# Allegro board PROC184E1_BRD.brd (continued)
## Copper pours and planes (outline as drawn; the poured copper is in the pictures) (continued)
MCU_ETH_EARTH on TOP: 61.78,9.23 61.78,12.4 85.17,12.4 85.17,9.23 85.15,9.25 81.85,9.25 81.36,9.74 79.15,9.74 78.6,9.18 78.6,0.76 70.9,0.76 70.9,9.25 70.26,9.89 68.28,9.89 67.62,9.23
MCU_ETH_EARTH on BOTTOM: 70.9,0.76 70.9,9.25 70.26,9.89 68.28,9.89 67.62,9.23 61.78,9.23 61.78,12.4 110.83,12.4 110.83,9.23 110.8,9.25 107.5,9.25 107.02,9.74 104.81,9.74 104.25,9.18 104.25,0.76 96.55,0.76 96.55,9.25 95.92,9.89 93.94,9.89 93.28,9.23 87.44,9.23 87.44,9.25 81.85,9.25 81.36,9.74 79.15,9.74 78.6,9.18 78.6,0.76
SW_LM5141 on TOP: 213.29,52.99 221.68,52.99 221.68,62.64 213.29,62.64
SW_LM5141 on BOTTOM: 213.29,52.99 221.04,52.99 221.04,62.64 213.29,62.64
USB0_VBUS_SOC on TOP: 138.62,177.76 138.62,176.28 140.48,176.28 140.48,177.76
USB0_VBUS_SOC on L5-SIGNAL2: 139.29,177.67 140.5,177.67 142.06,176.11 142.06,170.34 146.81,165.59 151.27,165.59 151.27,164.17 145.15,164.17 140.12,169.2 140.12,174.48 139.14,175.45 139.14,177.52
USB_FT2232_EARTH on TOP: 181.19,0.76 181.19,4.83 186.32,4.83 186.32,2.73 189.82,2.73 189.95,2.85 189.95,4.81 193.35,4.81 193.35,0.76
USB_FT4232_EARTH on TOP: 201.7,4.95 206.83,4.95 206.99,4.8 206.99,3.35 207.22,3.12 210.24,3.12 210.54,3.43 210.54,4.62 210.7,4.78 213.84,4.78 213.9,4.72 213.9,1.07 213.62,0.79 203.56,0.79 203.53,0.76 201.75,0.76 201.37,1.14 201.37,4.62
USB_TYPEA_EARTH1 on BOTTOM: 33.77,186.66 33.77,180.83 39.45,180.83 39.45,186.66
USB_TYPEA_EARTH1 on L7-SIGNAL3: 36.23,188.78 36.23,176.89 39.71,176.89 39.71,182.07 41.21,183.57 47.74,183.57 49.13,182.18 49.13,176.89 52.74,176.89 52.74,188.78
USBC_EARTH on TOP: 143.54,186.37 143.54,189.74 156.73,189.74 156.73,186.37
USBC_EARTH on BOTTOM: 143.72,181.62 143.72,189.74 157.16,189.74 157.16,186.75 155.3,186.75 155.3,181.64 155.28,181.62 152.76,181.62 152.76,186.39 145.8,186.39 145.8,181.62
USBC_PD_SW on TOP (solid shape): 172.92,176 173.03,175.95 173.12,175.94 173.86,175.94 173.92,175.94 173.99,175.96 174.11,175.96 174.15,175.95 174.16,175.91 174.16,174.12 174.15,174.09 174.11,174.07 173.41,174.07 173.38,174.04 173.38,174.04 173.33,174.04 173.31,174.03 173.3,174.02 173.22,173.95 173.21,173.94 173.19,173.93 172.17,173.93 172.13,173.95 172.12,173.98 172.12,175.94 172.13,175.98 172.17,176
USBC_PD_SW on BOTTOM (solid shape): outline of 631 points within 161.7,173.82 173.82,179.99
V_3V3 on TOP: 170.06,169.27 184.46,169.27 184.46,162.97 174.86,162.97 172.78,160.89 172.78,140.55 175.45,137.88 184.51,137.88 184.51,131.45 165.03,131.45 165.03,164.24
V_3V3 on BOTTOM, L7-SIGNAL3: 170.06,169.27 184.46,169.27 184.46,162.97 174.86,162.97 172.78,160.89 172.78,140.55 175.45,137.88 184.51,137.88 184.51,131.63 168.66,131.63 165.03,135.26 165.03,164.24
V_12V0 on TOP: 227.14,64.79 232.85,64.79 232.85,72.04 227.14,72.04
VBUS_5V_WIFI/BT on TOP: 131.33,188.74 131.33,184.56 133.43,184.56 133.43,188.74
VBUS_5V_WIFI/BT on BOTTOM: 130.74,188.65 130.74,181.47 134.07,181.47 134.07,188.65
VBUS_5V_WIFI/BT on BOTTOM: 137.99,178.09 137.99,176.99 137.4,176.99 137.4,176.11 139.09,176.11 139.09,178.09
VBUS_5V_WIFI/BT on L8-PWR1: 130.81,188.62 134.24,188.62 134.24,184.68 137.98,180.94 137.98,178.47 139,177.45 139,174.28 133.92,174.28 130.81,177.38
VCAP_VDDS2 on L14-SIGNAL6: 101.58,75.51 104.76,75.51 106.36,77.11 111.29,77.11 112.4,78.23 112.4,78.99 112.2,79.2 105.42,79.2 104.91,78.69 102.73,78.69 101.58,77.55
VCOMAD on L12-SIGNAL5: 21.83,27.54 41.49,27.54 41.49,24.62 39.4,22.54 29.62,22.54 29.62,19.64 31.76,19.64 32.19,19.21 32.19,11.89 30.69,11.89 30.69,14.94 26.88,18.75 26.88,24.54 22.84,24.54 22.31,24.01 22.31,15.12 19.19,15.12 19.19,24.9
VDA_DLL_MMC0_0V8 on BOTTOM: 157.06,103.31 157.06,102.67 159.7,102.67 159.7,103.31
VDA_DSITX_0V8 on BOTTOM: 116.75,107.8 117.97,107.8 118.09,107.67 118.09,106.3 117.97,106.17 116.8,106.17 116.42,106.55 115.38,106.55 115.38,107.44 116.39,107.44
VDA_MCU_1V8 on L8-PWR1: 112.13,75.98 101.05,75.98 99.39,74.32 99.07,74.32 99.07,47.7 107.25,39.52 115.71,39.52 116.44,38.79 131.15,38.79 132.29,37.64 163.96,37.64 164.29,38.02 175.72,49.45 175.72,50.21 182.61,57.11 182.61,74.02 178.88,77.76 169.64,77.76 169.35,77.47 169.35,53.5 158.91,43.06 144.31,43.06 140.34,47.02 140.34,57.13 128.35,69.11 116.57,69.11 114.77,70.92 114.77,75.72 114.51,75.98 114.49,75.98 114.06,76.4 112.56,76.4
VDA_PHY_1V8 on TOP: 106.43,111.78 106.43,109.72 108.28,109.72 108.28,111.78
VDA_PHY_1V8 on BOTTOM: 106.02,112.36 106.02,109.04 108.07,109.04 108.07,110.81 107.79,111.09 106.97,111.09 106.97,112.36
VDA_PHY_1V8 on L9-PWR2: 136.53,114.03 136.53,110.91 116.93,110.91 115.34,109.32 108.31,109.32 108.01,109.02 107.17,109.02 106.55,109.65 106.55,111.86 106.96,112.26 108.2,112.26 108.74,112.8 112.14,112.8 113.37,114.03
VDA_PHY_1V8 on L14-SIGNAL6: 155.62,107.16 155.62,102.7 170.82,102.7 170.82,107.16
VDA_PHY_1V8_REG on TOP: 108.8,115.16 107.83,115.16 107.83,114.45 106.41,114.45 106.41,112.05 108.8,112.05
VDA_PLL_1V8 on TOP: 87.98,82.14 90.86,82.14 90.86,84.05 87.98,84.05
VDA_PLL_1V8 on L12-SIGNAL5: 127.59,88.4 118.19,88.4 118.18,88.38 96.37,88.38 96.12,88.14 89.37,88.14 87.31,86.08 87.31,84.58 88.5,83.39 109.91,83.39 112.45,80.85 112.45,79.27 111.62,78.44 111.62,76.33 111.84,76.1 112.4,76.1 113.9,77.6 118.47,77.6 120.86,75.21 126.7,75.21 127.59,76.1
VDA_PLL_1V8_REG on TOP: 87.69,83.41 85.77,83.41 85.77,80.96 86.84,80.96 86.84,81.99 87.02,82.16 87.69,82.16
VDA_PLL_DDR1_0V8 on L10-SIGNAL4: 124.39,74.7 124.39,66.8 133.94,57.25 137.9,57.25 138.36,57.71 138.36,61.09 128.76,70.69 127.82,70.69 126.73,71.78 126.73,74.8 126.2,75.34 125.03,75.34
VDA_SERDES0_1_0V8 on BOTTOM: 134.46,107.75 135.89,107.75 135.89,106.19 134.52,106.19 134.17,106.54 133.11,106.54 133.11,107.45 133.14,107.48 134.19,107.48
VDA_SERDES0_1_0V8 on L9-PWR2: 134.2,107.08 136.43,107.08 136.43,93.96 131.02,88.54 124.42,88.54 123.91,89.05 123.91,89.69 124.29,90.07 124.67,90.07 125.18,89.56 126.2,89.56 133.31,96.67 133.31,106.19
VDA_SERDES0_1_1V8 on L9-PWR2: 130,101.3 130,107.07 131.94,107.07 132.93,106.08 132.93,96.93 127.47,91.47 127.47,91.08 126.2,89.81 124.93,89.81 124.93,91.73 126.07,92.86 126.07,97.37
VDA_SERDES4_0V8 on L9-PWR2: 126.24,104.83 126.44,105.03 126.44,105.66 127.81,107.04 129.28,107.04 129.5,106.83 129.5,103.84 128.48,102.83 126.14,102.83 123.84,100.52 123.78,98.87 123.78,93.31 124.29,92.8 124.29,90.7 123.15,89.56 121.39,89.56 120.56,90.4 120.56,102.29 123.1,104.83
VDA_SERDES_C0_1_0V8 on BOTTOM: 145.37,103.51 145.75,103.53 145.75,103.02 148.29,103.02 148.29,103.4 149.36,103.41 149.36,101.63 145.37,101.63
VDA_SERDES_C0_1_0V8 on L14-SIGNAL6: 123.88,89.15 123.88,88.62 125.23,87.27 129.7,87.27 130.46,86.51 138.24,86.51 141.05,89.33 141.05,96.55 144.84,100.33 146.08,100.33 147.23,101.47 147.23,101.85 146.9,102.18 144.05,102.18 139.61,97.74 139.61,89.94 137.55,87.88 131.33,87.88 129.57,89.64 124.37,89.64
VDA_UFS_0V8 on BOTTOM: 150.15,103.31 150.15,102.67 152.79,102.67 152.79,103.31
VDA_UFS_1V8 on BOTTOM: 153.6,103.31 153.6,102.67 156.24,102.67 156.24,103.31
VDA_USB_3V3_REG on BOTTOM: 117.43,116.09 117.43,117.05 118.14,117.05 118.14,118.47 119.95,118.47 119.95,116.09
VDA_USB_3V3_SEL on BOTTOM: 120.26,118.16 122.06,118.16 122.06,116.3 120.26,116.3
VEXP_3V3 on TOP: 203.06,125.53 203.06,118.52 217.86,118.52 217.86,126.7 205.88,126.7 205.88,125.53
VMAIN on TOP, L5-SIGNAL2, L10-SIGNAL4, L12-SIGNAL5, L14-SIGNAL6: 210.75,160.66 210.75,144.56 231.96,144.56 231.96,160.66
VMAIN on BOTTOM: 210.75,160.69 210.75,146.96 212.08,146.96 214.49,144.56 231.96,144.56 231.96,160.69
VMAIN on L3-SIGNAL1: 210.75,160.66 210.75,144.51 208.47,142.22 208.47,140.16 207.45,139.15 206.21,139.15 206.21,136.35 206.38,136.18 215.65,136.18 215.65,143.19 217.05,144.58 231.89,144.58 231.89,160.66
VMAIN on L7-SIGNAL3: 210.75,160.71 210.75,149.77 215.86,144.66 231.89,144.66 231.89,160.71
VMAIN_CONN on L3-SIGNAL1, L7-SIGNAL3, L8-PWR1, L10-SIGNAL4, L12-SIGNAL5, L14-SIGNAL6: 228.79,169.58 228.79,180.7 217.86,180.7 217.86,175.67 212.66,175.67 212.66,185.88 206.41,185.88 206.41,169.6 206.43,169.58
VMAIN_CONN on L5-SIGNAL2: 206.41,177.34 206.41,185.88 212.66,185.88 212.66,175.67 217.86,175.67 217.86,180.7 228.79,180.7 228.79,170.31 228.51,170.03 213.72,170.03
VMAIN_CONN on L9-PWR2: 228.79,169.55 228.79,180.7 217.66,180.7 217.66,175.67 212.63,175.67 212.63,185.88 206.41,185.88 206.41,175.88 212.73,169.55
VMAIN_FUSE on TOP: 215.22,161.3 228.79,161.3 228.79,168.94 208.49,168.94 208.49,165.31 209.07,165.31 209.07,166.63 210.19,166.63 210.19,165.18 215.22,165.18
VMAIN_FUSE on BOTTOM, L3-SIGNAL1, L8-PWR1, L10-SIGNAL4, L12-SIGNAL5, L14-SIGNAL6: 228.79,161.32 228.79,168.94 208.87,168.94 208.87,161.32
VMAIN_FUSE on L5-SIGNAL2: 228.79,161.32 228.79,168.83 208.87,168.83 208.87,161.32
VMAIN_FUSE on L7-SIGNAL3: 228.79,161.32 228.79,168.94 209.04,168.94 209.04,161.32
VMAIN_FUSE on L9-PWR2: 219.13,161.32 228.82,161.32 228.82,168.94 212.4,168.94 212.4,168.05
VPP_EFUSE_1V8 on TOP: 88.32,74.82 88.32,73.06 90.14,73.06 90.14,73.72 90.31,73.89 91.12,73.89 91.12,74.82
VPP_MCU_1V8 on L10-SIGNAL4: 105.39,70.47 109.14,70.47 111.03,72.37 113.39,72.37 113.95,71.81 113.95,68.43 112.3,66.78 100.87,66.78 100.67,66.98 100.67,66.99 100.44,67.22 100.43,67.22 99.67,67.98 99.67,68.5 103.42,68.5
VSYS_3V3 on TOP: 117.38,29.07 122.41,29.07 122.41,30.54 121.12,30.54 120.71,30.13 117.38,30.13
VSYS_3V3 on TOP: 112.28,118.52 111.06,119.74 78.14,119.74 78.14,130.97 141.59,130.97 143.82,133.21 143.82,141.03 149.44,146.64 149.44,156.6 164.65,156.6 164.65,131.42 161.59,131.42 160.08,129.9 160.08,118.52
VSYS_3V3 on TOP: 139.91,24.06 142.93,24.06 142.93,21.69 141.21,21.69 140.83,21.3 140.83,21.06 140.72,20.96 139.91,20.96
VSYS_3V3 on TOP: 29.83,129.18 29.83,123.76 31.3,123.76 31.3,125.38 32.36,126.44 65.56,126.44 65.56,129.18
VSYS_3V3 on TOP: 117.38,21.62 121.37,21.62 122.41,22.66 122.41,30.54 121.06,30.54 121.06,23.12 120.63,22.69 117.38,22.69
VSYS_3V3 on TOP: 12.97,134.22 12.97,133.14 15.47,133.14 15.47,134.22
VSYS_3V3 on BOTTOM: 154.14,156.45 154.14,149.16 153.98,149 153.98,139.96 164.42,139.96 164.42,156.45
VSYS_3V3 on BOTTOM: 86.22,127.74 82.19,127.74 82.19,128.81 86.22,128.81
VSYS_3V3 on BOTTOM: 12.94,135.21 12.94,133.08 15.55,133.08 15.55,135.21
VSYS_3V3 on L7-SIGNAL3: 61.72,127.73 64.85,127.73 65.72,126.85 65.72,112.43 67.27,110.88 67.27,105.55 61.72,105.55
VSYS_3V3 on L10-SIGNAL4: 143.14,156.7 194.93,156.7 219.19,132.44 219.19,129.06 222.28,125.97 222.28,92.74 186.52,92.74 184.46,94.8 184.46,102.7 198.18,102.7 198.18,117.38 192.77,122.79 156.65,122.79 143.14,136.3
VSYS_3V3 on L10-SIGNAL4: outline of 95 points within 45.58,3.94 240.24,189.59 ; 7 cut-outs
VSYS_3V3 on L12-SIGNAL5: 13.3,134.32 15.61,134.32 20.51,129.42 32.9,129.42 33.18,129.14 33.18,126.32 32.96,126.1 19.12,126.1 13.06,132.16 13.06,134.09
VSYS_5V0 on TOP: 221.29,90.51 221.29,82.2 226.37,82.2 226.37,85.07 227.47,85.07 227.47,90.51
VSYS_5V0 on TOP: 55.38,21.52 55.38,19.62 56.88,19.62 56.88,21.52
VSYS_5V0 on TOP: 73.29,91.02 72.14,91.02 71.89,90.76 69.1,90.76 69.1,92.29 72.14,92.29 72.14,91.52 73.29,91.52
VSYS_5V0 on TOP: 41,30.64 41,29.55 45.37,29.55 45.37,30.64
VSYS_5V0 on TOP: 24.29,7.58 24.29,3.72 25.74,3.72 25.74,7.58
VSYS_5V0 on TOP: 58.73,10.19 58.73,9.3 61.65,9.3 61.65,10.19
VSYS_5V0 on BOTTOM: 113.66,118.3 115.48,118.3 115.48,117.11 115.88,116.71 115.88,116.15 114.7,116.15 114.7,116.5 114.45,116.76 113.66,116.76
VSYS_5V0 on BOTTOM: 179.64,21.55 179.64,22.84 174.96,22.84 174.96,21.55
VSYS_5V0 on BOTTOM: 132.62,168.99 135.82,168.99 135.82,167.93 132.62,167.93
VSYS_5V0 on BOTTOM: 55.53,180.68 57.95,180.68 58.86,179.76 59.95,179.76 59.95,178.14 57.11,178.14 57.01,178.24 57.01,179.13 56.47,179.66 55.53,179.66
VSYS_5V0 on BOTTOM: 140.72,178.09 145.47,178.09 145.47,176.59 143.32,176.59 143.32,177.27 140.72,177.27
VSYS_5V0 on BOTTOM: 108.31,169.86 108.31,166.66 107.25,166.66 107.25,169.86
VSYS_5V0 on BOTTOM: 38.79,61.26 41.33,61.26 41.61,61.54 43.24,61.54 43.24,59.21 41.54,59.21 41.54,59.77 41.32,59.99 38.79,59.99
VSYS_5V0 on L7-SIGNAL3: 70.87,91.83 70.87,91.12 70.42,90.66 68.79,90.66 67.95,91.5 67.95,97.82 69.05,98.92 69.05,131.22 74.99,137.17 83.8,137.17 84.21,136.76 84.21,135.34 83.3,134.42 77.53,134.42 71.05,127.95 71.05,92.01
VSYS_5V0 on L9-PWR2: 24.29,3.39 24.29,15.02 28.99,19.72 28.99,63.15 41.39,75.55 41.39,117.48 53.48,117.48 53.48,66.94 43.62,57.08 43.62,36.63 84.77,36.63 93.86,27.54 107.91,27.54 108.97,26.47 128.35,26.47 129.4,25.43 140.37,25.43 140.88,25.94 157.34,25.94 157.84,25.43 169.81,25.43 170.48,24.76 186.36,24.76 188.68,27.08 218.12,27.08 229.55,38.51 229.55,79.92 227.59,81.87 219.08,81.87 219.08,128.46 181.26,166.28 98.69,166.28 96.66,168.31 44.92,168.31 44.92,188.29 192.55,188.29 211.34,169.5 211.34,167.72 218.88,160.18 223.91,160.18 242.86,141.23 242.86,9.4 236.85,3.39
VSYS_5V0 on L10-SIGNAL4: 69.22,94.21 72.95,97.94 75.95,97.94 101.57,123.57 107.17,123.57 107.17,122.91 91.42,107.17 91.42,103.44 88.38,100.39 85.92,100.39 79.21,93.68 73.7,93.68 73.16,93.15 73.16,91.68 72.3,90.81 69.22,90.81
VSYS_GPIORET_5V0 on TOP: 165.92,22.51 167.62,22.51 167.7,22.59 169.96,22.59 169.96,21.98 168.99,21.98 168.61,21.6 165.92,21.6
VSYS_GPIORET_IO_3V3 on BOTTOM: 80.76,67.55 80.76,66.48 80.63,66.35 80.63,64.73 81.9,64.73 81.9,67.42 81.77,67.55
VSYS_IO_1V8 on TOP: 54.26,108.64 55.69,108.64 55.69,109.61 54.26,109.61
VSYS_IO_1V8 on TOP: 101.38,156.01 101.38,151.44 102.24,151.44 102.24,156.01
VSYS_IO_1V8 on TOP: 61.43,109.92 60.61,109.92 60.61,108.26 61.43,108.26
VSYS_IO_1V8 on TOP: 167.95,89.82 170.62,89.82 170.62,88.55 169.86,87.79 169.86,87.28 169.73,87.15 167.95,87.15
VSYS_IO_1V8 on BOTTOM: 38.79,70.26 41.33,70.26 41.61,70.54 43.32,70.54 43.32,68.08 41.54,68.08 41.54,68.74 41.28,68.99 38.79,68.99
VSYS_IO_1V8 on BOTTOM: 139.58,157.87 139.58,154.46 139.86,154.19 140.27,154.19 140.5,154.41 140.5,154.97 140.62,155.1 140.95,155.1 141.49,155.63 142.5,155.63 142.5,157.87
VSYS_IO_1V8 on BOTTOM: 179.69,100.34 179.69,97.75 180.78,97.75 180.78,100.34
VSYS_IO_1V8 on L7-SIGNAL3: 104.31,163.91 104.31,152.28 103.54,151.51 83.05,151.51 83.05,151.54 77.45,151.54 77.45,151.37 69.55,143.46 69.55,137.59 66.72,134.76 66.72,130.53 64.55,128.37 61.11,128.37 61.11,107.27 54.2,107.27 54.2,131.12 57.03,133.94 57.03,140.55 80.38,163.91
VSYS_IO_1V8 on L8-PWR1: 152.08,175.67 204.91,175.67 204.91,167.93 178.11,167.93 175.89,165.7 175.89,158.29 173.85,156.24 82.33,156.24 80.63,157.94 80.63,169.25 82.79,171.41 147.81,171.41
VSYS_IO_1V8 on L10-SIGNAL4: 55.06,111.06 61.63,111.06 61.63,108.09 60,106.46 60,106.46 57.13,106.46 54.19,103.51 54.19,85.58 48.24,79.64 48.24,73.84 44.83,70.44 44.83,67.78 41.89,67.78 41.89,72.71 43.67,74.48 43.67,86.44 49.18,91.96 49.18,105.19
VSYS_IO_1V8 on L10-SIGNAL4: 183.78,97.16 174.46,97.16 172.73,95.44 172.73,88.04 168.33,88.04 167.57,88.81 167.57,102.67 183.78,102.67
VSYS_IO_1V8 on L14-SIGNAL6: 178.57,109.28 173.29,114.56 163.69,114.56 160.94,117.3 160.94,129.7 163.53,132.29 163.53,154.16 160.66,157.03 154.49,157.03 151.16,160.36 138.39,160.36 137.75,159.72 137.75,154.69 152.31,140.14 152.31,138.64 154.75,136.2 154.85,136.2 154.85,112.12 159.11,107.86 170.95,107.86 171.51,107.3 171.51,102.75 167.52,98.76 167.52,88.32 167.9,87.94 173.01,87.94 178.57,93.5
VSYS_IO_3V3 on TOP: 78.27,169.4 78.27,167.22 80.4,167.22 80.42,167.24 80.42,168.49 79.13,168.49 79.13,169.4
VSYS_IO_3V3 on TOP: 59.95,178.67 59.95,175.27 61.58,175.27 61.58,178.67
VSYS_IO_3V3 on TOP: 53.2,124.19 53.2,122.69 54.62,122.69 54.62,124.19
VSYS_IO_3V3 on TOP: 73.97,81.29 76.5,81.29 76.5,85.29 74.69,87.1 57.87,87.1 57.87,82.91 72.35,82.91
VSYS_IO_3V3 on TOP: 65.64,122.92 65.64,121.42 66.53,121.42 66.53,122.92
VSYS_IO_3V3 on BOTTOM: 132.65,157.2 131.3,157.2 131.3,162.29 132.65,162.29
VSYS_IO_3V3 on BOTTOM: 38.79,66.76 38.79,65.51 41.41,65.51 41.56,65.36 42.27,65.36 42.27,66.89 41.49,66.89 41.36,66.76
VSYS_IO_3V3 on BOTTOM: 152.43,151.8 153.78,151.8 153.78,157.31 154.24,157.77 156.4,157.77 156.4,160.18 152.43,160.18
VSYS_IO_3V3 on BOTTOM: 175.93,102.6 180.02,102.6 180.02,101.68 177.61,101.68 177.35,101.43 175.93,101.43
VSYS_IO_3V3 on BOTTOM: 136.79,28.13 136.79,24.39 137.96,24.39 137.96,28.13
VSYS_IO_3V3 on L7-SIGNAL3: 212.96,42.2 212.96,51.75 209.23,55.48 209.23,98.58 201.35,98.58 201.35,65.82 195.89,60.36 193.35,60.36 192.34,61.37 192.34,63.28 197.93,68.87 197.93,88.42 187.26,99.09 177.66,99.09 177.66,102.9 207.81,102.9 208.67,103.77 208.67,108.47 219.39,108.47 219.39,91.09 221.42,89.06 221.42,42.2
VSYS_IO_3V3 on L9-PWR2: 54.11,86.86 61.68,86.86 67.5,81.04 67.5,60.54 60.54,53.58 60.54,41.28 44.51,41.28 44.51,56.93 54.11,66.53
VSYS_IO_3V3 on L10-SIGNAL4: outline of 81 points within 6.37,1.35 220.28,189.06
VSYS_MCU_5V0 on TOP: 134.88,20.56 136.3,20.56 136.48,20.73 138.39,20.73 138.39,20.12 137.42,20.12 137.04,19.74 136.08,19.74 136.08,18.96 134.88,18.96
VSYS_MCU_5V0 on BOTTOM: 132.09,20.51 137.91,20.51 140.39,18.02 140.39,16.39 140.17,16.16 139.58,16.16 139.38,16.37 139.38,17.23 137.75,18.85 132.39,18.85 130.62,17.08 130.62,16.31 130.36,16.06 129.75,16.06 129.52,16.29 129.52,17.94
VSYS_MCU_5V0 on L7-SIGNAL3: 117.38,27.05 117.38,23.4 117.57,23.21 118.93,23.21 118.93,24.29 121.47,24.29 121.47,18.32 122.23,17.56 126.58,17.56 126.58,16.17 131.96,16.17 131.96,18.71 138.13,18.71 138.52,18.32 138.52,16.24 141.55,16.24 141.55,23.69 128.22,23.69 127.04,22.51 125.79,22.51 125.79,26.76 124.9,27.65 117.98,27.65
VSYS_MCUIO_1V8 on TOP: 165.25,69.45 165.25,68.21 166.58,68.21 166.58,69.45
VSYS_MCUIO_1V8 on L3-SIGNAL1: 130.08,41.02 130.08,38.1 130.64,37.54 135.75,37.54 137.97,39.76 142.79,39.76 145.17,42.14 145.17,47.37 144.86,47.68 144,47.68 143.67,47.35 143.67,44.68 142.73,43.74 139.78,43.74 138.44,45.09 138.44,46.33 138.16,46.61 135.82,46.61 135.39,46.18 135.39,43.87 133.76,42.24 131.3,42.24
VSYS_MCUIO_1V8 on L7-SIGNAL3: 128.35,41.4 128.35,37.11 129.5,35.97 136.86,35.97 144.64,43.74 144.64,50.5 141.13,54 138.18,54 133.08,48.9 133.08,43.26 131.99,42.16 129.12,42.16
VSYS_MCUIO_1V8 on L9-PWR2: 183.27,65.79 183.27,42.88 169.15,28.76 124.79,28.76 124.19,28.16 110.14,28.16 109.26,29.04 94.7,29.04 85.02,38.72 83.3,38.72 81.8,37.22 44.84,37.22 44.51,37.55 44.51,40.32 44.81,40.62 60.56,40.62 61.22,41.28 61.22,52.99 69.66,61.42 71.94,61.42 74.94,58.43 86.44,58.43 93.94,50.93 93.94,45.52 97.01,42.44 120.23,42.44 121.34,41.33 126.2,41.33 127.29,42.42 129.85,42.42 130.4,41.87 130.4,40.96 136.2,35.16 164.32,35.16 177.91,48.75 177.91,61.02 174.53,64.4 173.57,64.4 171.56,66.4 165.13,66.4 165.13,69.86 165.54,70.26 178.8,70.26
VSYS_MCUIO_3V3 on L7-SIGNAL3: 123.43,50.88 129.32,50.88 130.34,49.86 130.34,47.68 129.17,46.51 129.17,44.58 128.35,43.76 128.35,42.24 127.49,41.38 119.21,41.38 118.52,42.06 118.52,49.56 119.01,50.04 120.48,50.04 120.98,49.54 122.68,49.54 123.15,50.01 123.15,50.6
VSYS_MCUIO_3V3 on L7-SIGNAL3: 74.58,63.18 74.58,59.37 85.76,59.37 85.76,63.18
VSYS_MCUIO_3V3 on L8-PWR1: 168.69,71.14 168.69,76.23 167.83,77.1 167.83,77.73 169.44,79.34 181.61,79.34 183.29,81.03 183.29,86.57 190.81,86.57 193.15,84.23 193.15,51.77 172.78,31.4 92.01,31.4 86.88,36.53 86.88,52.26 83.19,55.94 83.19,62.9 83.04,62.9 82.38,63.56 82.38,71.99 81.82,72.55 73.16,72.55 72.55,73.16 72.55,84.3 51.49,84.3 51.49,20.53 53.98,18.04 85.89,18.04 87.38,16.54 87.38,3.06 91.04,3.06 91.04,16.52 92.57,18.04 107.83,18.04 109.63,16.24 109.63,4.63 112,4.63 112,16.42 113.62,18.04 126.58,18.04 126.58,7.48 199.53,7.48 199.53,85.81 192.06,93.28 171.43,93.28 164.73,86.57 164.73,72.96 166.54,71.14
VSYS_MCUIO_3V3 on L9-PWR2: 78.77,58.88 86.98,58.88 97.19,48.67 97.19,44.91 98.99,43.1 120.3,43.1 121.75,41.66 125.79,41.66 125.79,44.02 119.54,50.27 118.04,50.27 111.87,56.44 95.39,56.44 90.13,61.7 85.96,61.7 85.61,62.05 79.02,62.05 78.77,61.81
VSYS_VDDSHV2 on L5-SIGNAL2: 17.05,124.34 17.05,122.44 42.6,122.44 42.6,124.34
VSYS_VDDSHV2 on L9-PWR2: 56.85,96.5 56.85,125.13 41.44,125.13 41.44,118.45 54.14,118.45 54.14,88.86 55.46,87.53 61.92,87.53 68.16,81.29 68.16,62.69 77.45,62.69 77.45,65.24 73.27,65.24 71.22,67.29 71.22,82.13
VUSB_FT2232 on TOP: 189.77,7.3 191.14,7.3 191.14,5.16 189.67,5.16 189.67,3.41 189.19,3.41 189.19,5.37 188.86,5.7 188.86,6.48 189.77,6.48
VUSB_FT4232 on TOP: 209.81,3.44 209.81,5.57 210.22,5.98 211.59,5.98 211.77,6.15 211.77,6.46 211.84,6.54 212.71,6.54 212.94,6.76 213.77,6.76 213.77,5.34 210.63,5.34 210.27,4.99 210.27,3.44
VUSB_FT4232 on L7-SIGNAL3: 211.64,10.45 211.64,4.86 217.99,4.86 217.99,10.45
XDS_SHIELD on TOP: 15.45,189.6 15.45,185.74 18.43,185.74 18.43,188.09 21.82,188.09 21.82,185.67 28.14,185.67 28.14,189.6
N16860253 on TOP: 137.1,180.7 137.1,177.17 138.27,177.17 138.27,180.7
N33138535 on TOP: 61.96,182.05 61.96,177.32 66.23,177.32 66.23,182.05
N33442697 on BOTTOM: 18.96,38.34 18.96,36.96 21.42,36.96 21.42,38.34
N33442815 on BOTTOM: 18.96,35.8 18.96,34.42 21.42,34.42 21.42,35.8
N34888044 on TOP: 184.93,173.82 184.93,163.31 199.91,163.31 199.91,173.82
N34888105 on TOP: 184.9,137.9 184.9,132.16 187.53,129.52 201.07,129.52 201.07,137.9

Small or netless copper shapes (teardrops, artwork), in the pictures only: 1918 on TOP, 1228 on BOTTOM, 1 on L2-GND1, 1776 on L3-SIGNAL1, 985 on L4-GND2, 625 on L5-SIGNAL2, 280 on L7-SIGNAL3, 10 on L8-PWR1, 162 on L10-SIGNAL4, 599 on L12-SIGNAL5, 194 on L13-GND5, 714 on L14-SIGNAL6

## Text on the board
Ref Des/Assembly Bottom: BOTTOM ASSEMBLY | J742S2 EVALUATION MODULE BOTTOM ASSEMBLY REV. E1
Ref Des/Silkscreen Bottom: A | G | DGND | CONNECTOR | AUTOMATION | uSD CONN | FOR EVALUATION ONLY; | NOT FCC APPROVED FOR RESALE | CSI CONN | GESI BRD CONN
User.Comments: BOARD NAME: | J742S2/TDA4VPE/TDA4APE | EVALUATION MODULE | REV: E1 | DATE: 27/03/2024 | DESCRIPTION: | SHEET | OF | 23 | PROC184 | SCALE: 1 | CR_1_27 | CR_1_20 | CR_5_7 | TEXAS INSTRUMENTS | CR_TOP_NEW_1 | CR_SENSE_2 | CR_TPS74801DRCR_SON10_VSON10_TPS74_NEW_4 | CR_3_4 | CR_1_30 | CR_2_13 | CR_DUAL_PORT_FTDI_1 | CR_MCU_GB_ETH_2 | CR_AUDIO_IF_STEREO_OUT_1 | CR_TPS74801DRCR_SON10_VSON10_TPS74_1 | CR_TPS74801DRCR_SON10_VSON10_TPS74_NEW_2 | CR_TPS74801DRCR_SON10_VSON10_TPS74_2 | CR_JT14_PCIE0_CONN_1
Ref Des/Assembly Top: TOP ASSEMBLY | J742S2 EVALUATION MODULE TOP ASSEMBLY REV. E1
Ref Des/Silkscreen Top: VSYS_IO_3V3 | SPI | I3C | MCU_WAKE | J | SOC_INT2 | VSYS_3V3 | MCUIO_3V3 | EXT_PM | LIN | MCU_BOOT[2:9] | BOOT[0:7] | CAN | MCU_UART | UART | MAIN | MCU | SOC_INT1 | PORz | WARM | WAKE | EXP_PWR | MAIN_WAKE | JTAG_MIPI | ADC_HDR | MIC/HEADPHONE | RSV | PCIe1_CONN_x4L | PCIe0_CONN_x4L | BOOTMODE SW | CSI-TX CONN | USB-C | VIN NOMINAL | 24V TO 48V | PWR JACK | TEST AUTOMATION BELOW | XDS110 | USB-TYPE-A | RGMII1 | DISPLAY_PORT1 | MCU RGMII | DISPLAY_PORT0 | CONFIG SW | USER LED1 | USER LED2 | PWR LED | FAULT LED | OFF | ON | 12V FAN | uSD BELOW | J742S2/TDA4VPE/TDA4APE | EVALUATION MODULE | OPN# | ASSY | SL# | PCB# PROC184E1
PAGE_OUTLINE: LAYOUT BY | REVIEWED BY | APPROVED BY | SIGNATURES | GR | AMB | ZA | 270324 | DATE | SIZE | SCALE: | D | NONE | SHEET 1 OF 23 | PROC184E1 | Rev | E1 | J742S2/TDA4VPE/TDA4APE EVALUATION MODULE | TEXAS INSTRUMENTS
DIMENSION: DETAIL'A' | 17. | 16. | 10. | 11. | 12. | 13. | 14. | 15. | 1. | 2. | 3. | 4. | 5. | 6. | 7. | 8. | 9. | CONDUCTOR WIDTH SHALL NOT BE LESS THAN 20% FROM ITS ORIGINAL DATA. INCASE FOR MATCHING | IMPEDANCE MISTRAL SHALL APPROVE THE MODIFIED WIDTHS AND SPACING. | TRACE WIDTH SHALL BE MEASURED ON THE SURFACE IN CONTACT WITH THE LAMINATE. | AUTOMATED OPTICAL INSPECTION OF ALL THE LAYERS IS REQUIRED. | PCB SHALL BE MANUFACTURED USING I-SPEED OR EQUIVALENT. | BOW AND TWIST SHALL NOT EXCEED MORE THAN 0.75% OF THE DESIGN LENGTH. | FOR STACKUP DETAILS 'PROC141_STACKUP.PDF' SHALL BE REFERRED. | V-SCORE TO BE DONE AS PER DETAIL'A'. | FABRICATE PCB IN ACCORDANCE WITH IPC-6012C, CLASS 2; PER IPC-6011. | ALL UNCONNECTED VIA'S SHALL BE SUPPRESSED IN INTERNAL LAYERS. | FINISH: | MARKING: | ALL HOLES SHALL BE LOCATED WITHIN 0.15MM  DIAMETER OF TRUE POSITION. | LAYER TO LAYER REGISTRATION SHALL BE WITHIN 0.125MM. | MATERIALS: | ALL THE IMPEDANCE SHALL BE MATCHED AS PER IMPEDANCE TABLE WITH +/-10% TOLERANCE. | TEST REQUIREMENTS: | THIEVING IS ALLOWED ONLY IN THE PANEL FRAME, NOT IN THE CIRCUIT AREA. | TEAR DROPS SHALL BE ADDED ON INTERNAL AND EXTERNAL LAYER FOR ALL THE VIA'S AND THROUGH HOLE PADS. | FINISHED PCB THICKNESS SHALL BE 0.0850" +/-10%. | MIN TRACE WIDTH/SPACING ON BOARD IS 0.0031"/0.0033". | (MIN.TG 180) | ELECTROLESS NICKEL/IMMERSION GOLD, ELECTROLESS NICKEL SHALL BE 3-6 MICRONS, TYPICAL IMMERSION GOLD | THICKNESS SHALL BE 0.04-0.06 MICRONS OF SOLDERABLE IMMERSION GOLD SURFACE. | VIA'S, BLIND VIA'S SHALL NOT BE LESS THAN 12UM [0.00047"] AND BURIED VIA'S SHALL NOT BE LESS THAN 15UM [0.0006"]. | THE COPPER FOIL THICKNESS TOLERANCES SHALL BE AS PER IPC 6012B TABLE NO.3-7 AND 3-8. | LAMINATE AND PREPREG (B-STAGE) TO BE IN ACCORDANCE WITH IPC-4101/126. | ALL EXPOSED CONDUCTIVE PATTERN AREAS NOT COVERED WITH SOLDER MASK OR OTHER PLATING SHALL BE ENIG, | VIA HOLES THAT HAVE MASK OPEN SHALL BE FILLED WITH NON CONDUCTIVE INK AND CAP PLATED, | FOR OUTER LAYERS 1.45 OZ. COPPER WEIGHT IS TO BE CONSIDERED "FINISHED". | ONLY SOLDERMASK IMAGES THAT ARE 0.08(0.003") PER SIDE SHALL BE REDUCED IF REQUIRED. | COPPER FOIL TO BE IN ACCORDANCE WITH IPC-MF-150. UNLESS OTHERWISE SPECIFIED, | APPLY LIQUID PHOTO IMAGEABLE SOLDER MASK PER IPC-SM-840, CLASS H, TO BOTH SIDES OF THE BOARD OVER BARE COPPER. | ALL OTHER VIA HOLES SHALL BE FILLED WITH NON CONDUCTIVE INK AND COVERED WITH SOLDER MASK, | SILKSCREEN SHALL BE WHITE, PERMANENT, ORGANIC, NON-CONDUCTIVE INK. THERE SHALL BE | NO SILKSCREEN ON ANY SOLDERABLE COMPONENT PAD. CLIPPING OF SILK SCREEN SHALL BE ALLOWED | IF THE SILK SCREEN FALLS ON SOLDERABLE AREAS. | SURFACE AND VIA HOLES FINISH SHALL NOT BE LESS THAN 20UM [0.00079"], INCASE OF LASER | ALL HOLES SURROUNDED BY LAND <=0.010" SHALL BE COMPLAIN TO IPC6012, CLASS 2. | MANUFACTURER'S IDENTIFICATION AND DATE CODE LETTER SHALL BE RENDERED IN SILKSCREEN. | ALL OTHER SOLDER MASK IMAGES SHALL NOT BE ENLARGED. DEFAULT COLOUR OF SOLDER MASK SHALL BE GREEN. | BOARD SHALL MEET THE REQUIREMENTS OF UL-796E WITH FLAMMABILITY RATING OF MINIMUM 94V-0. UL LOGO,UL FILE NUMBER, | 100% NET LIST ELECTRICAL VERIFICATION USING MISTRAL SUPPLIED IPC-D-356 NET LIST FOR OPENS AND SHORTS. | FABRICATION NOTES:
User.6: SOM OUTLINE
User.8: TOP J7x FUSION2 SERIAL CAPTURE BOARD REV.E2
User.12: TPT37 | TPT38 | TPT41 | RT1 | RT3 | RT5 | RT8 | RT11 | RT13 | RT18 | RT25 | RT32 | RT44 | RT51 | RT54 | RT57 | RT65 | RT72 | RT86 | RT93 | RT102 | RT105 | RT112 | RT115 | RT118 | RT120 | RT131 | RT138 | RT145 | RT154 | RT158 | RT164 | RT169 | RT182 | RT195 | RT201 | RT207 | RT215 | RT220 | RT227 | TPT42 | YT5 | RT2 | RT4 | RT6 | RT9 | RT17 | RT24 | RT75 | CT58 | CT59 | CT65 | CT68 | CT73 | CT78 | CT85 | CT96 | CT104 | CT108 | CT110 | CT121 | CT130 | CT141 | CT150 | CT154 | CT155 | CT161 | CT168 | CT170 | CT174 | RT232 | CT182 | CT185 | CT187 | CT190 | CT192 | CT196 | CT197 | CT198 | CT202 | CT206 | CT209 | CT211 | CT216 | CT218 | CT221 | CT224 | CT227 | CT231 | CT236 | CT239 | CT242 | CT244 | CT249 | RT348 | RT370 | RT374 | RT381 | RT385 | RT392 | RT399 | RT423 | RT430 | RT433 | CT303 | RT458 | RT462 | RT481 | RT483 | RT488 | RT492 | RT499 | RT507 | RT511 | RT517 | RT526 | RT533 | RT539 | RT548 | RT555 | RT560 | RT562 | RT568 | RT572 | RT574 | CT13 | CT14 | CT28 | CT41 | CT48 | CT307 | JT8 | JT12 | UT11 | CT406 | QT10 | QT12 | QT13 | CT361 | CT369 | CT381 | CT396 | RT444 | UT34 | CT304 | CT343 | RT541 | RT549 | RT557 | RT561 | RT563 | RT570 | RT573 | CT282 | CT316 | CT322 | CT330 | CT353 | JT19 | JT21 | JT33 | JT7 | JT9 | TPT44 | TPT43 | TPT87 | TPT89 | JT15 | JT17 | TPT48 | TPT8 | JT34 | TPT47 | TPT11 | RT29 | RT316 | TPT12 | RT292 | RT282 | RT277 | RT262 | TPT30 | SWT12 | SWT10 | SWT11 | RT16 | TPT2 | RT540 | RT546 | RT550 | RT52 | CT29 | RT23 | TPT3 | CT18 | CT333 | JT20 | TPT74 | TPT5 | CT323 | CT19 | FLT21 | RT265 | RT270 | RT275 | RT279 | RT286 | RT288 | RT293 | RT298 | RT302 | RT305 | RT315 | RT322 | RT312 | RT260 | TPT56 | TPT60 | RT329 | TPT6 | UT1 | JT2 | TPT9 | TPT69 | TPT61 | CT232 | RT307 | RT299 | RT303 | RT261 | RT267 | RT271 | RT276 | RT280 | RT287 | RT289 | RT294 | TPT57 | RT317 | RT311 | CT229 | CT106 | TPT10 | CT152 | CT27 | CT75 | CT33 | RT334 | LDT2 | LDT1 | RT484 | CT338 | CT414 | RT527 | TPT52 | CT181 | CT248 | TPT23 | UT102 | TPT34 | CT234 | RT319 | RT324 | RT543 | RT537 | CT400 | TPT58 | RT386 | CT372 | CT340 | RT135 | UT107 | CT273 | RT538 | RT544 | TPT40 | JT38 | CT339 | CT306 | CT278 | RT522 | TPT54 | CT288 | CT296 | RT383 | FLT19 | CT267 | CT276 | RT137 | SWT3 | UT51 | CT317 | CT314 | UT101 | RT136 | CT413 | RT528 | JT10 | JT14 | TPT51 | CT308 | CT259 | RT387 | RT66 | RT70 | CT337 | RT320 | TPT59 | TPT70 | RT325 | CT213 | CT36 | CT269 | CT275 | CT261 | TPT71 | TPT76 | FLT20 | UT72 | CT309 | CT373 | RT335 | RT338 | FLT5 | TPT16 | RT45 | CT263 | TPT62 | JT4 | TPT15 | CT26 | CT32 | CT21 | CT25 | CT165 | RT162 | RT166 | RT163 | RT165 | RT183 | RT168 | RT197 | RT177 | RT189 | CT11 | YT4 | FLT9 | CT166 | CT133 | CT136 | CT142 | CT162 | CT143 | CT134 | CT137 | FLT10 | TPT73 | RT184 | RT186 | RT198 | RT170 | RT178 | RT190 | RT167 | CT87 | UT97 | RT185 | CT123 | RT92 | CT299 | CT297 | CT315 | TPT83 | FLT22 | CT319 | QT16 | TPT88 | RT475 | CT125 | RT476 | JT13 | CT220 | CT222 | TPT22 | RT236 | QT9 | CT225 | CT254 | JT35 | CT98 | RT422 | RT427 | RT62 | QT15 | RT64 | RT55 | RT498 | RT513 | RT516 | RT508 | RT510 | RT502 | TPT80 | RT494 | UT90 | RT420 | YT1 | UT100 | RT495 | CT341 | RT534 | TPT21 | TPT19 | YT2 | CT3 | MHT1 | JT1 | SWT2 | TPT25 | TPT97 | UT15 | TPT26 | TPT75 | RT27 | QT2 | RT203 | RT12 | DT6 | FLT13 | CT124 | CT116 | CT120 | YT3 | RT525 | RT146 | RT148 | DT7 | RT224 | JT3 | UT4 | DT8 | FLT25 | RT149 | RT147 | JT36 | RT26 | DT9 | QT1 | CT1 | CT151 | CT153 | CT146 | RT314 | RT19 | TPT4 | CT436 | CT438 | CT35 | RT46 | RT47 | RT53 | CT440 | RT536 | UT109 | RT295 | RT300 | UT116 | RT239 | TPT18 | CT44 | CT439 | CT402 | CT47 | UT13 | CT66 | CT408 | UT10 | UT83 | UT70 | UT77 | UT61 | UT65 | CT42 | RT28 | UT57 | TPT31 | CT270 | CT214 | CT53 | CT49 | RT418 | RT520 | CT20 | RT378 | RT382 | RT323 | RT328 | RT366 | RT369 | RT332 | RT337 | RT342 | RT344 | RT306 | RT309 | CT176 | CT147 | JT37 | UT37 | CT61 | RT242 | TPT78 | LT1 | UT86 | CT22 | UT71 | UT63 | UT75 | UT81 | UT59 | UT89 | UT53 | TPT24 | CT148 | CT376 | TPT14 | UT105 | RT246 | RT247 | RT251 | RT254 | RT255 | RT257 | RT264 | RT269 | RT321 | RT326 | CT336 | TPT17 | RT421 | RT426 | RT439 | RT365 | RT367 | RT375 | RT380 | RT331 | RT336 | RT343 | RT345 | RT388 | RT390 | CT5 | TPT98 | RT206 | CT149 | TPT85 | TPT84 | RT71 | CT292 | RT443 | CT109 | CT71 | CT397 | YT6 | CT378 | CT411 | RT489 | CT52 | CT432 | QT5 | JT40 | TPT95 | QT6 | CT419 | RT435 | CT264 | UT79 | QT7 | QT4 | UT31 | RT95 | RT263 | TPT81 | RT429 | CT189 | TPT13 | CT171 | RT290 | CT437 | TPT1 | LDT10 | CT184 | RT547 | CT403 | CT204 | TPT49 | RT208 | CT84 | RT566 | LT2 | RT210 | SWT4 | SWT6 | TPT63 | CT69 | TPT96 | CT4 | CT193 | TPT46 | UT43 | CT399 | TPT50 | TPT33 | CT107 | CT129 | CT293 | CT294 | TPT64 | TPT86 | RT209 | RT111 | TPT36 | CT194 | UT3 | UT94 | RT256 | YT7 | CT398 | CT412 | LT6 | RT133 | CT105 | TPT45 | JT41 | TPT66 | CT301 | TPT68 | CT379 | CT302 | TPT67 | CT122 | SWT5 | SWT7 | TPT20 | CT279 | CT283 | LDT11 | FT2 | CT359 | JT18 | RT567 | CT349 | CT188 | CT175 | UT111 | CT422 | CT435 | RT479 | JT5 | CT82 | RT273 | CT208 | CT205 | RT266 | CT201 | CT200 | CT284 | CT195 | CT280 | RT96 | RT449 | QT8 | RT480 | RT459 | DT12 | TPT82 | TT1 | CT300 | UT14 | RT153 | UT24 | CT380 | CT404 | CT99 | TPT93 | DT13 | CT298 | LT4 | DT5 | LT5 | UT48 | QT11 | CT327 | JT39 | CT368 | RT391 | RT398 | RT400 | RT419 | RT424 | RT428 | UT23 | RT532 | CT199 | CT320 | CT374 | RT132 | DT10 | RT500 | RT97 | RT509 | RT441 | RT436 | TPT35 | RT446 | FT1 | UT21 | CT328 | RT283 | TPT94 | RT278 | RT253 | CT321 | RT61 | UT45 | TPT79 | RT125 | CT172 | CT183 | CT157 | JT11 | TPT90 | SWT1 | TPT65 | RT442 | CT287 | RT33 | CT34 | CT37 | UT2 | UT18 | UT20 | UT32 | FLT16 | FLT17 | UT25 | UT28 | RT259 | RT268 | RT274 | RT281 | RT297 | RT304 | RT310 | RT318 | RT327 | RT330 | RT333 | RT339 | RT340 | RT346 | RT347 | RT368 | RT373 | RT379 | RT384 | RT389 | RT397 | RT417 | RT425 | RT434 | RT440 | RT450 | UT7 | UT17 | UT8 | JT22 | UT41 | UT67 | UT73 | UT84 | UT91 | UT66 | UT55 | UT9 | UT6 | UT26 | UT39 | CT97 | CT131 | UT27 | CT132 | UT12 | UT112 | UT19 | UT22 | UT87 | UT54 | UT5 | UT47 | UT29 | UT40 | UT35 | UT44 | UT95 | CT390 | UT99 | UT114 | QT3 | UT110 | UT104 | UT36 | UT49 | UT46 | UT113 | JT23 | RT571 | JT16 | UT106 | UT16 | UT93 | RT252 | JT24 | UT98 | JT32 | UT103 | UT108 | UT92 | CT119 | RT296 | RT308 | RT14 | RT21 | RT15 | RT301 | RT313 | RT20 | RT30 | RT48 | RT7 | RT10 | RT139 | CT72 | RT49 | RT140 | CT30 | TPT7 | FBT1 | RT141 | CT31 | CT15 | RT142 | CT16 | CT17 | CT324 | CT326 | RT234 | CT325 | RT464 | CT179 | RT465 | CT357 | RT466 | RT530 | RT521 | CT382 | RT542 | CT318 | RT512 | CT409 | CT395 | RT473 | RT474 | RT235 | CT350 | RT472 | RT241 | CT358 | RT471 | RT463 | RT216 | RT211 | CT101 | CT401 | TPT53 | RT217 | CT102 | CT410 | RT212 | RT514 | RT545 | RT67 | CT389 | CT50 | RT228 | RT531 | CT271 | CT43 | RT229 | RT490 | CT272 | RT455 | RT467 | CT344 | CT240 | RT456 | RT468 | CT331 | RT371 | CT217 | RT376 | CT247 | RT457 | RT377 | RT372 | RT56 | RT50 | CT312 | RT58 | RT341 | CT268 | FLT18 | CT334 | RT113 | TPT55 | RT114 | CT158 | CT159 | FLT14 | RT193 | CT160 | RT194 | RT199 | RT187 | CT12 | CT163 | CT164 | TPT32 | FLT15 | RT129 | CT177 | RT460 | RT200 | RT130 | RT188 | CT295 | LDT8 | RT245 | RT461 | RT230 | CT345 | RT213 | CT360 | RT231 | LDT9 | RT214 | CT347 | RT126 | RT106 | RT127 | RT128 | CT362 | CT383 | RT223 | TPT77 | RT107 | CT384 | CT156 | RT160 | RT108 | CT351 | CT385 | RT491 | RT485 | CT386 | RT171 | RT109 | CT387 | RT172 | RT161 | RT110 | RT486 | CT388 | RT493 | RT173 | RT174 | RT175 | RT60 | CT285 | RT176 | TPT27 | RT63 | TPT28 | CT286 | CT38 | CT46 | RT159 | RT477 | CT407 | CT329 | RT564 | RT478 | CT289 | CT290 | CT355 | CT291 | RT529 | CT342 | CT356 | RT116 | FLT12 | RT117 | FLT11 | FLT6 | RT34 | RT76 | RT35 | RT77 | CT89 | RT191 | CT90 | RT36 | RT78 | CT76 | CT70 | RT37 | RT79 | CT91 | RT192 | CT92 | RT38 | RT80 | CT93 | RT39 | RT81 | RT98 | RT123 | RT40 | RT82 | RT99 | RT124 | CT60 | FLT1 | RT41 | RT83 | CT94 | RT100 | RT42 | RT84 | CT95 | RT101 | RT43 | RT85 | CT2 | DT3 | DT1 | FLT7 | RT524 | FLT24 | FLT8 | FLT3 | DT25 | CT138 | CT126 | DT26 | RT143 | DT17 | CT117 | RT180 | CT127 | CT139 | RT144 | CT118 | RT181 | CT128 | CT140 | DT18 | FLT4 | TPT29 | DT27 | FLT29 | RT150 | DT28 | RT151 | DT4 | RT179 | DT19 | RT22 | DT2 | FLT26 | DT20 | FLT2 | DT29 | RT152 | FLT30 | RT157 | DT30 | CT428 | CT144 | TPT91 | CT135 | RT535 | RT518 | RT240 | RT218 | RT59 | RT221 | RT244 | RT558 | RT243 | RT396 | RT222 | RT219 | RT395 | CT391 | RT559 | UT76 | UT64 | UT82 | UT69 | UT56 | UT60 | TPT92 | RT31 | CT392 | RT569 | CT393 | RT519 | CT223 | CT243 | CT250 | CT256 | CT262 | CT226 | CT235 | DT31 | FLT23 | CT238 | CT253 | CT258 | CT230 | CT245 | CT39 | DT32 | CT23 | RT202 | RT94 | DT21 | UT38 | CT40 | FLT27 | RT225 | DT22 | CT24 | RT226 | DT33 | UT62 | UT74 | UT58 | CT173 | UT80 | UT68 | UT85 | UT88 | FLT31 | UT52 | CT169 | RT237 | DT34 | CT191 | DT23 | CT180 | FLT28 | RT238 | DT24 | CT266 | CT228 | CT277 | CT281 | CT252 | CT237 | CT246 | DT35 | CT257 | CT212 | CT178 | CT313 | CT219 | CT251 | CT255 | CT241 | CT260 | CT274 | CT233 | RT437 | RT496 | DT36 | RT487 | FLT32 | CT186 | RT497 | CT352 | RT482 | CT9 | RT204 | CT51 | CT145 | RT196 | CT370 | CT10 | RT205 | CT417 | CT429 | CT425 | CT354 | CT364 | RT553 | CT433 | CT365 | UT30 | CT420 | LT3 | RT73 | RT272 | CT421 | TPT39 | RT393 | RT74 | CT6 | RT551 | CT215 | QT14 | RT394 | CT265 | CT431 | UT78 | CT7 | DT14 | DT11 | CT167 | RT401 | RT506 | CT377 | RT349 | CT8 | RT233 | RT350 | RT402 | CT77 | RT291 | CT415 | CT103 | RT351 | RT403 | CT416 | RT352 | RT404 | CT427 | RT134 | RT250 | RT353 | RT405 | CT100 | RT354 | RT88 | RT406 | RT248 | RT445 | CT67 | CT367 | RT355 | RT407 | LDT7 | RT249 | UT42 | CT63 | RT408 | RT356 | CT371 | RT89 | CT86 | SWT8 | CT79 | CT64 | LDT6 | RT414 | CT418 | CT88 | RT453 | CT74 | RT358 | CT430 | RT431 | RT87 | RT451 | RT359 | RT415 | CT426 | LDT5 | RT452 | CT434 | RT360 | RT416 | CT363 | RT361 | RT554 | RT409 | CT310 | CT54 | RT432 | RT362 | RT121 | RT410 | RT448 | CT113 | CT366 | RT363 | RT411 | RT122 | CT55 | CT423 | RT364 | RT412 | CT114 | RT119 | DT16 | CT424 | RT357 | RT413 | CT56 | CT80 | RT258 | RT552 | CT115 | CT311 | TPT72 | CT57 | SWT9 | RT90 | RT155 | CT81 | RT503 | RT447 | RT454 | RT91 | CT210 | RT469 | RT504 | CT394 | RT505 | RT284 | RT285 | RT103 | CT83 | RT104 | CT207 | RT470 | CT111 | CT62 | CT203 | CT405 | DT15 | RT515 | CT112 | CT375 | CT305 | RT501 | RT523 | RT68 | UT96 | LDT3 | RT69 | RT438 | JT25 | JT28 | LDT4 | JT30 | JT31 | CT45 | CT332 | CT335 | RT556 | CT346 | CT348 | UT50 | UT33 | RT565 | UT115 | JT27 | RT156 | JT6 | JT26 | JT29 | BOARD NAME: | J7X COMMON PROCESSOR BRD | REV: A | DATE: 17/11/2021 | DESCRIPTION: | SHEET | PRIMARY-SIDE-Assembly | 1 | OF | 2 | PROC079 | SCALE: 1 | PROC079 TOP ASSEMBLY REV.A | TEXAS INSTRUMENTS
User.13: CARD EJECTED | CARD LOCK | CARD OVER STROCK | RB25 | RB24 | RB17 | RB127 | RB135 | RB130 | RB141 | CB8 | CB24 | CB10 | RB34 | YB1 | RB111 | RB147 | CB9 | CB87 | RB139 | CB146 | CB23 | RB146 | RB100 | RB159 | RB177 | CB51 | RB2 | RB1 | CB86 | RB90 | RB108 | RB109 | RB52 | RB101 | CB83 | RB74 | RB173 | RB120 | CB143 | RB190 | RB192 | CB158 | UB25 | CB137 | RB166 | RB226 | CB205 | CB4 | CB47 | RB236 | RB231 | RB191 | CB112 | RB96 | CB188 | CB193 | RB259 | CB195 | RB258 | RB233 | CB199 | CB16 | CB13 | FLB3 | RB97 | YB3 | FB2 | FB1 | CB191 | CB187 | CB189 | RB202 | RB205 | CB21 | CB30 | CB32 | CB34 | RB107 | RB235 | CB129 | RB261 | RB262 | UB74 | JB5 | JB1 | CB20 | CB22 | CB29 | CB31 | RB35 | CB33 | RB217 | RB216 | RB228 | CB194 | CB196 | RB225 | RB232 | QB3 | CB168 | RB10 | CB185 | CB2 | CB3 | RB201 | BB1 | CB111 | RB133 | CB219 | UB1 | TPB15 | RB256 | CB79 | CB73 | CB70 | FLB1 | CB161 | CB84 | RB145 | QB1 | CB71 | YB2 | UB31 | CB80 | RB56 | TPB1 | TPB2 | TPB3 | CB218 | RB50 | CB220 | CB102 | RB117 | TPB9 | TPB11 | CB97 | CB101 | RB64 | CB95 | TPB10 | FLB6 | RB115 | RB155 | RB150 | RB183 | RB153 | RB144 | CB92 | CB94 | CB96 | RB158 | RB162 | RB140 | RB149 | RB179 | RB170 | RB172 | RB119 | DB2 | CB98 | RB121 | CB44 | CB103 | RB131 | RB102 | RB103 | CB40 | RB84 | UB10 | CB110 | CB127 | TPB12 | TPB13 | TPB7 | CB89 | TPB14 | UB9 | TPB6 | TPB5 | TPB4 | RB197 | RB168 | RB194 | RB178 | RB157 | RB189 | RB154 | RB181 | RB161 | RB152 | RB185 | CB224 | RB122 | RB118 | RB207 | CB175 | FB6 | RB206 | RB129 | FB5 | CB171 | RB148 | RB123 | RB134 | CB115 | RB48 | RB51 | CB150 | CB210 | RB75 | RB71 | RB112 | CB109 | RB114 | CB133 | CB149 | CB178 | CB223 | RB73 | RB184 | CB93 | CB160 | JB6 | CB177 | UB6 | CB15 | CB108 | JB2 | RB200 | CB132 | RB237 | FB4 | RB186 | CB120 | CB107 | CB148 | CB124 | CB229 | FB3 | CB147 | CB226 | CB222 | CB38 | CB201 | CB212 | UB8 | CB45 | JB3 | UB5 | UB45 | UB23 | UB21 | RB18 | UB77 | UB4 | CB126 | UB71 | UB2 | UB67 | UB30 | UB7 | CB85 | UB22 | UB81 | UB73 | UB72 | UB78 | UB70 | CB172 | UB63 | CB106 | UB24 | UB80 | CB173 | UB61 | CB105 | UB66 | UB62 | UB75 | UB79 | JB4 | RB22 | CB5 | CB25 | RB126 | CB6 | RB14 | RB8 | RB11 | UB76 | RB63 | RB78 | CB28 | RB45 | RB62 | RB77 | RB110 | CB192 | RB61 | RB88 | RB76 | RB60 | CB27 | RB44 | RB16 | RB89 | RB85 | CB88 | CB7 | RB15 | RB33 | RB99 | RB66 | RB82 | RB72 | RB156 | RB32 | RB174 | RB91 | RB55 | RB81 | RB31 | RB80 | RB167 | CB46 | RB30 | RB79 | CB215 | CB53 | RB163 | CB49 | RB165 | RB160 | RB54 | RB95 | RB169 | CB82 | CB48 | CB142 | RB94 | RB53 | RB164 | RB93 | RB193 | RB188 | RB222 | RB243 | CB81 | RB203 | RB187 | RB221 | RB242 | RB241 | RB227 | RB59 | CB207 | RB98 | RB65 | CB200 | CB214 | CB213 | RB229 | CB184 | CB198 | CB206 | RB224 | RB240 | CB183 | RB220 | RB239 | RB219 | RB238 | RB223 | RB182 | RB92 | RB23 | CB174 | CB35 | CB41 | CB182 | CB221 | TPB16 | RB212 | RB105 | RB211 | RB106 | CB37 | RB104 | CB204 | RB210 | CB197 | CB36 | CB19 | RB209 | CB190 | RB43 | RB204 | CB18 | RB208 | RB42 | RB41 | RB40 | RB86 | CB17 | RB39 | RB38 | RB215 | CB163 | CB180 | RB214 | CB179 | RB213 | CB170 | FLB2 | CB119 | CB217 | RB132 | RB125 | RB138 | RB253 | RB128 | CB64 | RB137 | RB252 | CB63 | CB78 | CB69 | RB136 | CB66 | CB113 | CB76 | CB65 | RB21 | CB77 | CB166 | CB164 | FLB4 | CB122 | CB72 | CB62 | CB68 | CB75 | CB121 | CB74 | CB67 | RB143 | RB142 | FLB5 | CB227 | CB208 | RB27 | CB26 | UB54 | UB36 | UB33 | UB44 | UB59 | UB49 | RB26 | UB32 | RB29 | UB60 | RB28 | UB37 | UB43 | UB50 | UB55 | CB118 | CB131 | CB141 | CB156 | CB125 | CB152 | RB58 | RB69 | CB14 | CB123 | CB128 | CB136 | CB145 | CB116 | CB154 | RB47 | RB257 | RB68 | CB43 | UB12 | RB67 | RB255 | RB87 | CB42 | RB254 | CB104 | UB11 | UB68 | UB65 | UB42 | UB47 | UB58 | UB52 | CB54 | UB28 | CB99 | RB83 | UB41 | UB69 | UB27 | RB116 | CB50 | RB37 | TPB8 | UB57 | CB91 | UB64 | UB48 | UB53 | CB130 | CB140 | CB167 | CB159 | CB155 | CB151 | CB55 | RB36 | CB144 | CB153 | CB157 | CB165 | CB135 | CB114 | RB171 | CB100 | RB251 | RB250 | RB249 | RB180 | CB186 | RB248 | CB202 | RB234 | CB209 | CB117 | RB196 | CB134 | CB176 | RB195 | RB124 | RB151 | RB113 | QB2 | RB46 | RB13 | RB247 | RB9 | CB11 | RB246 | RB49 | RB20 | CB1 | RB176 | RB245 | RB19 | RB57 | UB3 | RB7 | RB198 | RB244 | DB1 | RB6 | CB90 | RB70 | CB12 | RB5 | RB12 | CB169 | RB4 | RB199 | RB230 | CB228 | CB211 | RB218 | CB203 | CB60 | CB59 | CB225 | CB139 | CB58 | DB4 | RB260 | RB175 | CB138 | DB3 | CB57 | CB56 | CB39 | UB46 | UB56 | UB51 | UB16 | CB52 | UB20 | UB15 | CB216 | UB14 | UB19 | UB18 | UB13 | CB181 | CB162 | UB29 | UB34 | RB3 | CB61 | UB17 | UB38 | UB26 | UB35 | UB40 | UB39 | UB82 | PROC079 | 2 | OF | SECONDARY-SIDE-Assembly | SHEET | DESCRIPTION: | DATE: 17/11/2021 | REV: A | J7X COMMON PROCESSOR BRD | BOARD NAME: | SCALE: 1 | TEXAS INSTRUMENTS | PROC079 BOTTOM ASSEMBLY REV.A
User.19: B | A | C | D
User.20: G
